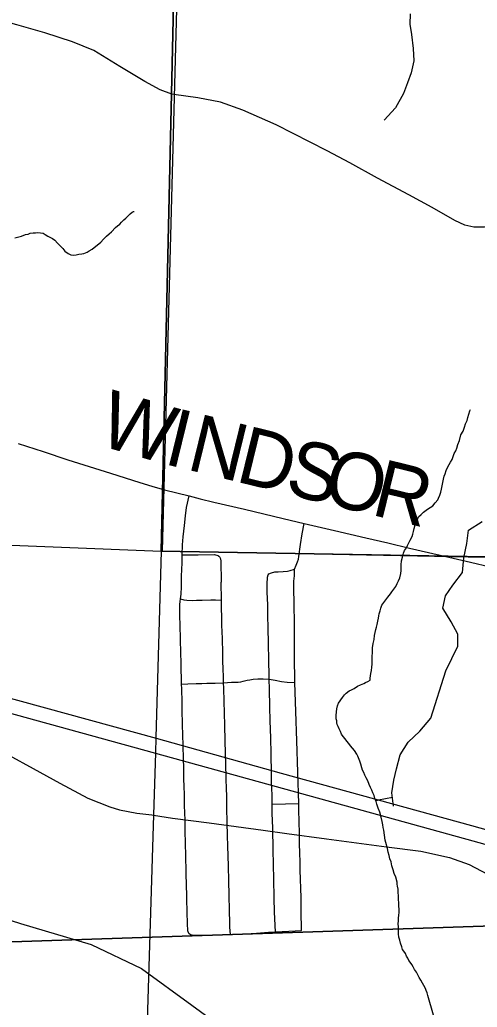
# Model space of a CAD drawing. Extents: x -6.1 to 38, y -7.7 to 22.
# Drawn here: x 7.886 to 8.34, y 19.438 to 20.415 of the extents above; entities that cross this region are included whole.
import ezdxf

# ---------------------------------------------------------------- set-up
doc = ezdxf.new("R2010")
doc.units = 0
for name, color, linetype in [('GM_X_Corporation', 7, 'Continuous'), ('GM_X_County_Road', 7, 'Continuous'), ('GM_X_County_Road_Text', 7, 'Continuous'), ('GM_X_Minor_River', 7, 'Continuous'), ('GM_X_Rail_Line', 7, 'Continuous'), ('GM_X_Township_Road', 7, 'Continuous'), ('GM_X_US_Route', 7, 'Continuous')]:
    doc.layers.add(name, color=color, linetype=linetype)

msp = doc.modelspace()

# ---------------------------------------------------------------- linework, layer by layer
at = {"layer": 'GM_X_Corporation'}
for points in [[(6.8881, 19.93659), (7.17492, 19.92346), (7.23616, 19.921), (8.02661, 19.88922), (8.03683, 20.34208), (8.04941, 20.9), (3.3101, 20.9)], [(6.8881, 19.93659), (7.17492, 19.92346), (7.23616, 19.921), (8.02661, 19.88922), (8.02125, 19.70471), (8.02079, 19.68982), (8.0189, 19.62846), (7.99279, 18.77986), (7.97287, 17.92154), (7.97183, 17.87641), (7.95308, 17.06692), (7.95307, 17.06643), (7.93594, 16.3267), (7.92512, 16.10977), (7.91657, 15.91251), (7.90988, 15.74002), (7.90533, 15.62285), (7.88899, 15.0865), (7.88923, 14.89059), (7.27984, 14.90301), (6.7864, 14.92029)]]:
    msp.add_lwpolyline(points, dxfattribs=at)
for points in [[(8.9, 19.53649), (8.9, 20.9), (6.96628, 20.9), (6.97445, 20.38052), (6.97563, 20.30513), (6.97663, 20.24175), (6.9774, 20.19314), (6.99327, 19.47331), (8.77312, 19.53228), (8.77571, 19.53237)], [(8.9, 19.87135), (8.9, 20.9), (8.04941, 20.9), (8.03683, 20.34208), (8.02661, 19.88922), (8.53815, 19.88018)], [(8.38678, 20.9), (8.05557, 20.9), (8.05523, 20.88915), (8.04569, 20.57586), (8.02764, 19.88943), (8.26371, 19.88485), (8.85075, 19.87347), (8.9, 19.87251), (8.9, 20.88601)], [(8.9, 14.85918), (8.9, 19.87135), (8.53815, 19.88018), (8.02661, 19.88922), (8.02125, 19.70471), (8.02079, 19.68982), (8.0189, 19.62846), (7.99279, 18.77986), (7.97287, 17.92154), (7.97183, 17.87641), (7.95308, 17.06692), (7.95307, 17.06643), (7.93594, 16.3267), (7.92512, 16.10977), (7.91657, 15.91251), (7.90988, 15.74002), (7.90533, 15.62285), (7.88899, 15.0865), (7.88923, 14.89059), (8.1023, 14.88375), (8.27757, 14.87811), (8.6137, 14.86789)], [(8.9, 14.68725), (8.9, 19.53649), (8.77571, 19.53237), (8.77312, 19.53228), (6.99327, 19.47331), (6.99349, 19.46054), (7.03821, 16.8882), (7.05054, 16.17866), (7.07262, 15.21743), (7.07601, 15.03919), (7.07603, 15.03845), (7.07902, 14.88093), (7.08348, 14.64684), (7.55487, 14.65733), (8.5875, 14.68029)]]:
    msp.add_lwpolyline(points, close=True, dxfattribs=at)
at = {"layer": 'GM_X_County_Road'}
for points in [[(8.03903, 20.34126), (8.03704, 20.34154), (8.02539, 20.34562), (8.01048, 20.35417), (7.98562, 20.36888), (7.9597, 20.38467), (7.93887, 20.39335), (7.91146, 20.40209), (7.88363, 20.41004), (7.84843, 20.41978)], [(8.43218, 20.21291), (8.42464, 20.21379), (8.38845, 20.21161), (8.3467, 20.20982), (8.33627, 20.2099), (8.32744, 20.21191), (8.31741, 20.21652), (8.29513, 20.22937), (8.27186, 20.242), (8.24072, 20.25833), (8.21349, 20.27345), (8.19092, 20.28537), (8.14031, 20.31103), (8.10731, 20.32574), (8.08524, 20.33349), (8.06297, 20.33786), (8.03903, 20.34126)], [(7.88492, 19.99592), (7.90953, 19.9878), (7.93414, 19.97968), (7.95531, 19.97303), (7.97647, 19.96637), (8.00527, 19.95717), (8.01738, 19.95365), (8.02998, 19.94997), (8.05429, 19.94387), (8.0651, 19.94108), (8.07877, 19.93783), (8.109, 19.93068), (8.12824, 19.92613), (8.14748, 19.92158), (8.1681, 19.91676), (8.19836, 19.90972), (8.2139, 19.90611), (8.22944, 19.9025), (8.25097, 19.89735), (8.2725, 19.89219), (8.30277, 19.88521), (8.33304, 19.87822), (8.35233, 19.87377)], [(7.61518, 19.81605), (7.61297, 19.80194), (7.61275, 19.79377), (7.61371, 19.78565), (7.61695, 19.77679), (7.62472, 19.76989), (7.63281, 19.768), (7.64501, 19.7701), (7.65494, 19.77053), (7.66315, 19.76945), (7.68214, 19.7632), (7.74151, 19.74268), (7.79461, 19.72455), (7.82483, 19.71398), (7.84447, 19.70448), (7.87556, 19.68721), (7.89974, 19.67404), (7.92627, 19.65966), (7.95398, 19.64481), (7.97576, 19.63639), (7.98522, 19.63324), (8.00249, 19.63), (8.01715, 19.62817)], [(8.01715, 19.62817), (8.01911, 19.62792), (8.03789, 19.62504), (8.07416, 19.6205), (8.12748, 19.61317), (8.15101, 19.60993), (8.1903, 19.60453), (8.24966, 19.59676), (8.28377, 19.59244), (8.31227, 19.58596), (8.3317, 19.57927), (8.34983, 19.56956)]]:
    msp.add_lwpolyline(points, dxfattribs=at)
at = {"layer": 'GM_X_Minor_River'}
for points in [[(8.27331, 20.42097), (8.27295, 20.41073), (8.2745, 20.40049), (8.27605, 20.38685), (8.27684, 20.37434), (8.27422, 20.36258), (8.27047, 20.35271), (8.26672, 20.34208), (8.25882, 20.32803), (8.2475, 20.31586)], [(7.88162, 20.19936), (7.88804, 20.20099), (7.89219, 20.20259), (7.89485, 20.20302), (7.89673, 20.20381), (7.89976, 20.20425), (7.90204, 20.20429), (7.90393, 20.2047), (7.90697, 20.20437), (7.90964, 20.20404), (7.91156, 20.20255), (7.91425, 20.20108), (7.91693, 20.19961), (7.91885, 20.1985), (7.92116, 20.19702), (7.92387, 20.19403), (7.92696, 20.19104), (7.92928, 20.1888), (7.93123, 20.18618), (7.93431, 20.18395), (7.93699, 20.18248), (7.93966, 20.18215), (7.94231, 20.18257), (7.94496, 20.183), (7.94799, 20.18344), (7.94988, 20.18385), (7.95328, 20.18505), (7.95515, 20.1866), (7.95816, 20.18818), (7.96677, 20.19518), (7.96938, 20.19789), (7.97236, 20.20098), (7.97498, 20.20331), (7.97722, 20.20525), (7.98132, 20.20951), (7.98319, 20.21106), (7.98544, 20.213), (7.9873, 20.21494), (7.98954, 20.21726), (7.99141, 20.21881), (7.99328, 20.22037), (7.99589, 20.22307), (7.99776, 20.22463), (7.99927, 20.22542), (7.99965, 20.22542)], [(8.20207, 19.73893), (8.20615, 19.74433), (8.208, 19.74702), (8.20987, 19.74858), (8.21287, 19.75091), (8.21513, 19.75209), (8.21777, 19.75328), (8.22114, 19.75562), (8.22416, 19.75682), (8.22717, 19.75839), (8.22905, 19.75919), (8.23131, 19.76037), (8.23357, 19.76155), (8.23354, 19.76345), (8.23421, 19.76803), (8.23492, 19.77108), (8.23524, 19.77451), (8.23556, 19.77755), (8.23549, 19.78136), (8.23543, 19.78516), (8.23574, 19.78897), (8.23603, 19.79353), (8.23672, 19.79773), (8.2374, 19.80192), (8.23772, 19.80573), (8.23842, 19.80878), (8.23912, 19.81184), (8.23984, 19.81413), (8.24055, 19.81681), (8.24126, 19.81986), (8.24196, 19.82292), (8.2423, 19.8252), (8.24265, 19.82711), (8.24335, 19.83017), (8.24406, 19.83284), (8.24515, 19.8359), (8.25109, 19.84361), (8.25368, 19.84708), (8.25517, 19.84901), (8.25702, 19.8517), (8.25887, 19.8544), (8.26034, 19.85709), (8.26181, 19.85977), (8.2629, 19.86284), (8.26396, 19.86704), (8.26428, 19.87008), (8.26424, 19.87275), (8.26418, 19.87579), (8.26449, 19.8796), (8.26556, 19.88342), (8.26664, 19.88724), (8.26773, 19.88992), (8.26958, 19.89261), (8.27067, 19.89491), (8.27177, 19.8976), (8.27324, 19.90028), (8.27507, 19.90374), (8.27579, 19.90603), (8.2765, 19.90871), (8.27721, 19.91176), (8.27829, 19.9152), (8.27938, 19.91788), (8.2801, 19.9198), (8.28156, 19.92325), (8.28418, 19.92558), (8.28641, 19.9279), (8.28904, 19.92984), (8.29129, 19.93141), (8.29317, 19.93258), (8.2958, 19.93415), (8.29802, 19.93723), (8.30063, 19.93994), (8.30136, 19.94185), (8.30245, 19.94453), (8.30353, 19.94759), (8.30424, 19.95065), (8.30634, 19.96057), (8.30704, 19.96363), (8.30776, 19.96592), (8.30884, 19.96898), (8.31031, 19.97205), (8.31177, 19.97512), (8.31325, 19.97743), (8.31472, 19.98011), (8.31581, 19.98279), (8.3169, 19.98586), (8.31837, 19.98854), (8.31946, 19.99122), (8.32054, 19.99467), (8.32198, 19.99887), (8.3234, 20.00422), (8.32561, 20.00807), (8.32706, 20.01189), (8.32814, 20.01533), (8.32961, 20.0184), (8.33031, 20.02146), (8.33139, 20.0249), (8.33247, 20.02796), (8.33282, 20.02949)], [(8.25662, 19.63682), (8.25507, 19.65008), (8.25692, 19.6626), (8.25953, 19.67398), (8.26328, 19.68764), (8.27118, 19.70017), (8.28287, 19.7112), (8.2938, 19.72412), (8.30842, 19.7708), (8.32045, 19.7951), (8.32041, 19.80723), (8.31395, 19.81935), (8.30559, 19.83297), (8.3082, 19.84511), (8.31536, 19.85575), (8.32515, 19.86829), (8.32625, 19.8827), (8.32923, 19.89674), (8.33109, 19.91001), (8.34468, 19.91877)], [(8.30178, 19.41067), (8.29082, 19.44964), (8.29001, 19.45229), (8.28921, 19.45455), (8.28842, 19.45644), (8.28372, 19.46472), (8.28215, 19.46736), (8.28096, 19.47), (8.2794, 19.47263), (8.27745, 19.47526), (8.27626, 19.4779), (8.2747, 19.48015), (8.27314, 19.4824), (8.27197, 19.48428), (8.27079, 19.48654), (8.26962, 19.48842), (8.26843, 19.49107), (8.26687, 19.49332), (8.2657, 19.4952), (8.26489, 19.49785), (8.26369, 19.50125), (8.26288, 19.50427), (8.26206, 19.5073), (8.26162, 19.51072), (8.26156, 19.51414), (8.2615, 19.51756), (8.26144, 19.5206), (8.26177, 19.52327), (8.26173, 19.52593), (8.26205, 19.52897), (8.26238, 19.53164), (8.26232, 19.53506), (8.26189, 19.5381), (8.26183, 19.54114), (8.26177, 19.54456), (8.26171, 19.54798), (8.26126, 19.55178), (8.26121, 19.55482), (8.26077, 19.55785), (8.26036, 19.55974), (8.26033, 19.56164), (8.2591, 19.56657), (8.25751, 19.57034), (8.25631, 19.57374), (8.2551, 19.5779), (8.25427, 19.58169), (8.25307, 19.58471), (8.25225, 19.58812), (8.25143, 19.59152), (8.25061, 19.59493), (8.24899, 19.60099), (8.24856, 19.60326), (8.24725, 19.61312), (8.24644, 19.61577), (8.24601, 19.61843), (8.24557, 19.62184), (8.24436, 19.626), (8.24313, 19.63092), (8.24154, 19.63508), (8.24033, 19.63886), (8.23952, 19.6415), (8.23833, 19.64452), (8.23751, 19.64755), (8.23633, 19.65019), (8.23514, 19.65283), (8.23396, 19.65547), (8.23276, 19.65849), (8.23118, 19.66189), (8.22961, 19.6649), (8.22842, 19.66754), (8.22723, 19.67018), (8.22605, 19.67244), (8.22525, 19.67471), (8.22443, 19.6785), (8.22323, 19.68151), (8.22125, 19.68642), (8.22045, 19.68831), (8.21811, 19.69207), (8.21617, 19.69432), (8.21423, 19.69656), (8.21229, 19.69881), (8.21035, 19.70106), (8.20878, 19.70369), (8.20684, 19.70594), (8.20528, 19.70819), (8.2041, 19.71083), (8.20291, 19.71347), (8.20173, 19.71573), (8.20093, 19.71762), (8.20052, 19.71951), (8.20049, 19.72141), (8.20007, 19.72331), (8.20001, 19.72673), (8.20033, 19.73016), (8.20066, 19.7332), (8.20136, 19.73626), (8.20207, 19.73893)], [(8.25562, 19.64536), (8.24185, 19.64284), (8.23958, 19.64208)]]:
    msp.add_lwpolyline(points, dxfattribs=at)
at = {"layer": 'GM_X_Rail_Line'}
msp.add_lwpolyline([(6.19287, 19.69813), (6.21792, 19.65768), (6.25419, 19.613), (6.2935, 19.58374), (6.34004, 19.56589), (6.38312, 19.55199), (6.4273, 19.55367), (6.48418, 19.56365), (6.64401, 19.60019), (6.71957, 19.61741), (6.76764, 19.62675), (6.84656, 19.6383), (7.43863, 19.63931), (7.50222, 19.63795), (7.56146, 19.62521), (7.63701, 19.60108), (7.88712, 19.52077), (7.95726, 19.49994), (8.00695, 19.47618), (8.05679, 19.43987), (8.28809, 19.27109), (8.78458, 18.9138), (8.9, 18.83346)], dxfattribs=at)
at = {"layer": 'GM_X_Township_Road'}
msp.add_line((8.13655, 19.63904), (8.16285, 19.6395), dxfattribs=at)
for points in [[(8.09512, 19.50987), (8.08394, 19.50921), (8.06783, 19.50887), (8.05875, 19.50906), (8.0557, 19.50964), (8.05404, 19.51101), (8.05305, 19.51356), (8.05268, 19.52065), (8.05244, 19.53191), (8.05207, 19.54513), (8.05165, 19.56193), (8.05146, 19.56701), (8.05123, 19.57305), (8.05091, 19.5869), (8.05049, 19.60127), (8.05035, 19.61103), (8.05022, 19.62292), (8.0498, 19.63769), (8.04961, 19.64812), (8.04933, 19.65685), (8.0491, 19.66371), (8.04901, 19.67443), (8.04873, 19.6841), (8.04831, 19.69644), (8.04813, 19.70773), (8.04775, 19.71699), (8.04766, 19.72046), (8.04748, 19.72962), (8.04739, 19.73998), (8.04702, 19.75304), (8.04678, 19.75779), (8.04654, 19.76347), (8.04641, 19.77176), (8.04632, 19.7797), (8.04604, 19.7877), (8.04571, 19.80277), (8.04529, 19.81525), (8.04497, 19.82603), (8.04507, 19.83645), (8.04526, 19.8395), (8.04559, 19.8422), (8.04644, 19.8467), (8.04669, 19.85397), (8.04684, 19.86446), (8.04722, 19.87786), (8.04736, 19.88555), (8.04775, 19.89551), (8.04842, 19.90344), (8.04956, 19.91457), (8.05071, 19.9241), (8.05161, 19.9323), (8.05429, 19.94387)], [(8.09512, 19.50987), (8.10541, 19.51039), (8.12104, 19.51126), (8.13278, 19.51213), (8.13966, 19.51264), (8.13872, 19.53194), (8.13864, 19.54603), (8.13817, 19.56476), (8.13757, 19.59381), (8.13706, 19.61513), (8.13664, 19.63), (8.13655, 19.63904), (8.13642, 19.64809), (8.136, 19.66003), (8.13577, 19.67467), (8.13554, 19.68294), (8.13535, 19.6887), (8.13516, 19.70447), (8.1346, 19.72136), (8.13414, 19.73519), (8.13381, 19.75274), (8.13358, 19.76271), (8.13349, 19.76594), (8.13331, 19.78136), (8.1328, 19.79792), (8.13267, 19.81354), (8.13234, 19.82524), (8.13211, 19.8363), (8.13169, 19.84859), (8.1316, 19.85671), (8.13177, 19.86364), (8.13253, 19.86586), (8.13335, 19.86677), (8.13568, 19.86797), (8.13918, 19.86871), (8.14254, 19.86896), (8.14738, 19.86914), (8.1516, 19.86941), (8.15425, 19.87006), (8.15866, 19.87128), (8.16018, 19.87547), (8.16165, 19.87866), (8.16245, 19.88122), (8.16293, 19.88402), (8.16469, 19.89583), (8.16636, 19.90626), (8.1681, 19.91676)], [(8.04736, 19.88555), (8.06331, 19.88574), (8.07925, 19.88594), (8.08257, 19.88504), (8.08276, 19.88492), (8.08295, 19.88481), (8.08304, 19.88474), (8.08324, 19.88461), (8.08333, 19.88453), (8.08342, 19.88446), (8.08352, 19.8844), (8.08366, 19.88425), (8.08376, 19.88417), (8.08385, 19.8841), (8.08399, 19.88393), (8.08409, 19.88385), (8.08423, 19.88368), (8.08437, 19.88351), (8.08452, 19.88334), (8.08466, 19.88315), (8.08489, 19.88277), (8.08579, 19.87956), (8.08602, 19.85871)], [(8.13966, 19.51264), (8.15313, 19.51322), (8.16567, 19.51377), (8.16521, 19.53335), (8.16508, 19.54665), (8.16438, 19.57344), (8.1641, 19.58157), (8.16386, 19.59063), (8.16368, 19.59975), (8.16359, 19.6085), (8.16332, 19.62292), (8.16304, 19.6317), (8.16293, 19.63588), (8.16285, 19.6395), (8.16185, 19.67055), (8.16085, 19.7016), (8.15992, 19.73047), (8.15899, 19.75933), (8.15876, 19.78536), (8.15863, 19.80298), (8.15849, 19.8206), (8.1584, 19.83389), (8.15799, 19.85607), (8.15813, 19.8594), (8.15832, 19.8622), (8.15856, 19.86482), (8.15866, 19.87128)], [(8.09512, 19.50987), (8.09456, 19.51706), (8.09442, 19.52133), (8.09418, 19.53365), (8.09382, 19.54878), (8.09349, 19.56307), (8.09321, 19.57745), (8.09266, 19.59757), (8.09233, 19.60743), (8.09196, 19.62094), (8.09164, 19.63483), (8.09145, 19.64771), (8.09126, 19.6533), (8.09089, 19.66449), (8.09061, 19.67895), (8.09029, 19.68906), (8.08991, 19.70184), (8.0895, 19.71677), (8.08927, 19.72917), (8.08885, 19.74041), (8.08866, 19.75357), (8.08843, 19.75899), (8.08824, 19.7643), (8.08791, 19.77358), (8.08773, 19.77968), (8.0875, 19.78816), (8.08722, 19.80268), (8.08675, 19.81608), (8.08615, 19.84092), (8.08602, 19.85871)], [(8.04559, 19.8422), (8.04886, 19.84119), (8.05204, 19.84066), (8.05772, 19.84046), (8.0617, 19.84061)], [(8.0617, 19.84061), (8.0672, 19.84081), (8.07572, 19.84121), (8.08051, 19.84107), (8.08615, 19.84092)], [(8.04678, 19.75779), (8.05308, 19.7579), (8.06118, 19.75818), (8.06678, 19.75838), (8.0718, 19.75857), (8.08009, 19.75877), (8.08843, 19.75899), (8.0962, 19.75948), (8.10278, 19.75971), (8.10534, 19.75996), (8.1079, 19.76045), (8.11184, 19.76147), (8.11444, 19.76196), (8.1178, 19.76255), (8.12238, 19.76288), (8.12764, 19.76301), (8.13358, 19.76271), (8.13953, 19.76154), (8.14577, 19.76019), (8.15152, 19.75958), (8.15899, 19.75933)]]:
    msp.add_lwpolyline(points, dxfattribs=at)
at = {"layer": 'GM_X_US_Route'}
for points in [[(7.61518, 19.81605), (7.75881, 19.77617), (7.84307, 19.75294), (8.02146, 19.70417), (8.14551, 19.66955), (8.33405, 19.61765), (8.39877, 19.59963), (8.47646, 19.57811), (8.51624, 19.56662), (8.53644, 19.5601), (8.56055, 19.55141), (8.59116, 19.53752), (8.61201, 19.52623), (8.63133, 19.51472), (8.65305, 19.50017), (8.67195, 19.48583), (8.70734, 19.45869), (8.7762, 19.40454), (8.81092, 19.37747), (8.83437, 19.36054), (8.85131, 19.34924), (8.87781, 19.33405), (8.9, 19.32297)], [(7.61297, 19.80194), (7.8397, 19.73927), (8.021, 19.68928), (8.33536, 19.60266), (8.45631, 19.569), (8.51146, 19.55337), (8.54187, 19.5436), (8.55884, 19.53655), (8.5701, 19.53187), (8.58552, 19.52471), (8.61397, 19.50929), (8.64067, 19.4917), (8.66261, 19.47563), (8.79225, 19.37444), (8.80745, 19.36293), (8.82829, 19.34773), (8.84567, 19.33643), (8.86087, 19.3271), (8.88128, 19.31624), (8.9, 19.30747)]]:
    msp.add_lwpolyline(points, dxfattribs=at)

# ---------------------------------------------------------------- texts
at = {"layer": 'GM_X_County_Road_Text'}
for s, rotation, p in [('W', 343.91133, (7.96198, 19.99488)), ('I', 346.22764, (8.02765, 19.97599)), ('N', 346.23597, (8.05033, 19.97043)), ('D', 346.23597, (8.09889, 19.95854)), ('S', 346.23474, (8.14745, 19.94664)), ('O', 346.23322, (8.18468, 19.93752)), ('R', 346.23403, (8.23325, 19.92562))]:
    msp.add_text(s, height=0.05682, rotation=rotation, dxfattribs=at).set_placement(p)

doc.saveas('drawing.dxf')
